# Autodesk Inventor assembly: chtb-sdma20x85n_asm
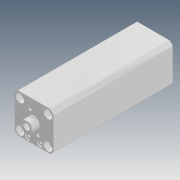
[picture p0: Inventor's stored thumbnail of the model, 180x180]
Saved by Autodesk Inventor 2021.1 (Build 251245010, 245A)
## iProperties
Created: 2018-05
Part Number: chtb-sdma20x85n_asm
Description: STEP AP214
Document SubType Name: Assembly
Designer: user
Title: chtb-sdma20x85n_asm.STEP
Revision Number: ÈÎºÎ
Sending System: SolidWorks 2016
Preprocessor: SwSTEP 2.0
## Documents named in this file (5)
- D:\Vault_2016\Projekty\Clamptek\Hydraulic\CHTB\CHTB-20\Inventor\CHTB-SDMA20x85N\chtb-sdma20x85n_asm.iam
- D:\Vault_2016\Projekty\Clamptek\Hydraulic\CHTB\CHTB-20\Inventor\CHTB-SDMA20x85N\CHTB-SDMA20X85NBT.ipt
- D:\Vault_2016\Projekty\Clamptek\Hydraulic\CHTB\CHTB-20\Inventor\CHTB-SDMA20x85N\CHTB-SDMA20X85NHSG.ipt
- D:\Vault_2016\Projekty\Clamptek\Hydraulic\CHTB\CHTB-20\Inventor\CHTB-SDMA20x85N\QG_3.ipt
- D:\Vault_2016\Projekty\Clamptek\Hydraulic\CHTB\CHTB-20\Inventor\CHTB-SDMA20x85N\socket set screw flat point_iso_ISO 4026 - M5 x 5-N.ipt
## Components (5 placed, 5 different names)
1. CHTB-SDMA20X85NBT_1
2. CHTB-SDMA20X85NHSG_2
3. QG_3_3
4. socket set screw flat point_iso_ISO 4026 - M5 x 5-N_4
5. socket set screw flat point_iso_ISO 4026 - M5 x 5-N_5
